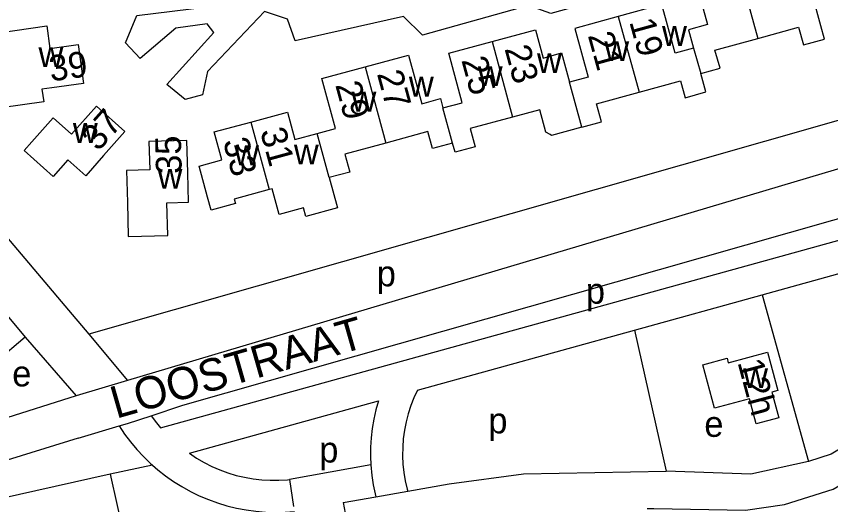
# Model space of a CAD drawing. Extents: x 162883 to 165538, y 383986 to 385172.
# Drawn here: x 164417 to 164543.6, y 384557.3 to 384633.2 of the extents above; entities that cross this region are included whole.
import ezdxf

# ---------------------------------------------------------------- set-up
doc = ezdxf.new("R2010")
doc.units = 0
for name, color, linetype in [('BLT_Basislijn', 7, 'Continuous'), ('BLT_Bebouwing', 7, 'Continuous'), ('BLT_Centroide', 7, 'Continuous'), ('BLT_Huisnummer', 7, 'Continuous'), ('BLT_Huisnummer_ tussenligend', 7, 'Continuous'), ('BLT_Onderverdeling_panden', 7, 'Continuous'), ('BLT_Straatnaam', 7, 'Continuous')]:
    doc.layers.add(name, color=color, linetype=linetype)

msp = doc.modelspace()

# ---------------------------------------------------------------- linework, layer by layer
at = {"layer": 'BLT_Basislijn'}
for p, q in [((164553.59, 384619.51), (164428.29, 384583.78)), ((164404.43, 384611.88), (164424.57, 384588.23)), ((164553.06, 384611.91), (164434.29, 384576.61)), ((164439.44, 384569.26), (164555.69, 384601.4)), ((164533, 384589.94), (164556.66, 384596.48)), ((164513.11, 384584.44), (164533, 384589.94)), ((164533, 384589.94), (164540.17, 384564.04)), ((164424.57, 384588.23), (164428.29, 384583.78)), ((164428.29, 384583.78), (164434.29, 384576.61)), ((164479.4, 384575.12), (164513.11, 384584.44)), ((164513.11, 384584.44), (164518.06, 384562.5)), ((164418.37, 384583.33), (164426.33, 384574.22)), ((164434.29, 384576.61), (164426.33, 384574.22)), ((164426.33, 384574.22), (164414.53, 384570.51)), ((164437.95, 384571.13), (164442.92, 384572.76)), ((164443.91, 384565.3), (164473.33, 384573.44)), ((164434.29, 384569.93), (164437.95, 384571.13)), ((164433, 384569.54), (164434.29, 384569.93)), ((164426.61, 384567.64), (164433, 384569.54)), ((164426.61, 384567.64), (164401.23, 384559.81)), ((164438.18, 384563.46), (164431.59, 384562.05)), ((164472.13, 384563.52), (164459.46, 384561.22)), ((164459.46, 384561.22), (164460.12, 384557.04)), ((164467.83, 384557.63), (164472.93, 384558.53)), ((164472.93, 384558.53), (164477.88, 384559.41)), ((164467.83, 384557.63), (164468.82, 384552.21))]:
    msp.add_line(p, q, dxfattribs=at)
for points in [[(164530.02, 384655.67), (164523.39, 384654.01), (164524.91, 384648.14), (164519.33, 384646.51), (164517.95, 384644.09), (164519.33, 384638.96), (164500.12, 384633.64), (164496.67, 384634.86), (164480.18, 384630.26), (164477.19, 384633.17), (164460.34, 384629.38), (164459.19, 384632.74), (164455.61, 384633.93)], [(164455.61, 384633.93), (164446.71, 384624.64), (164445.93, 384620.98), (164443.27, 384620.28), (164440.41, 384622.61), (164447.71, 384630.68), (164446.66, 384632.04), (164441.79, 384631.37), (164436.24, 384626.66), (164433.96, 384629.09), (164435.76, 384633.33), (164449.67, 384635.02), (164451.25, 384637.34)], [(164442.92, 384572.76), (164550.7, 384603.45), (164555.04, 384604.67)], [(164479.4, 384575.12), (164478.84, 384573.92), (164478.36, 384572.7), (164477.95, 384571.44), (164477.62, 384570.16), (164477.36, 384568.87), (164477.18, 384567.56), (164477.09, 384566.24), (164477.07, 384564.92), (164477.13, 384563.6), (164477.27, 384562.29), (164477.49, 384560.99), (164477.8, 384559.7), (164477.88, 384559.41)], [(164556.18, 384575.94), (164554.59, 384573.48), (164549.66, 384568.74), (164543.71, 384565.14), (164540.17, 384564.04)], [(164473.33, 384573.44), (164472.93, 384572.03), (164472.6, 384570.61), (164472.35, 384569.16), (164472.17, 384567.71), (164472.08, 384566.25), (164472.07, 384564.79), (164472.13, 384563.52)], [(164437.95, 384571.13), (164438.79, 384570.03), (164439.44, 384569.26)], [(164515.11, 384556.74), (164516.15, 384556.71), (164530.41, 384556.48), (164536.46, 384557.35), (164544, 384559.73), (164552.89, 384564.9), (164556.58, 384566.59), (164561.28, 384567.83), (164564.73, 384567.77), (164568.27, 384566.96), (164569.42, 384569.95)], [(164433, 384569.54), (164433.85, 384568.28), (164434.76, 384567.06), (164435.74, 384565.9), (164436.78, 384564.78), (164437.87, 384563.73), (164438.18, 384563.46)], [(164443.91, 384565.3), (164445.03, 384564.55), (164446.19, 384563.87), (164447.39, 384563.26), (164448.63, 384562.72), (164449.89, 384562.26), (164451.18, 384561.87), (164452.49, 384561.56), (164453.82, 384561.33), (164455.16, 384561.17), (164456.5, 384561.1), (164457.85, 384561.11), (164459.19, 384561.19), (164459.46, 384561.22)], [(164438.18, 384563.46), (164439.02, 384562.73), (164440.22, 384561.79), (164441.47, 384560.92), (164442.76, 384560.11), (164444.09, 384559.37), (164445.46, 384558.71), (164446.87, 384558.11), (164448.3, 384557.6), (164449.75, 384557.15), (164451.23, 384556.79), (164452.73, 384556.5), (164454.24, 384556.29), (164455.75, 384556.16), (164457.27, 384556.11), (164458.8, 384556.14), (164460.27, 384556.25)], [(164472.13, 384563.52), (164472.29, 384561.87), (164472.51, 384560.42), (164472.82, 384558.99), (164472.93, 384558.53)], [(164540.17, 384564.04), (164531.21, 384562.04), (164518.06, 384562.5)], [(164477.88, 384559.41), (164484.31, 384560.55), (164495.89, 384562.12), (164518.06, 384562.5)]]:
    msp.add_lwpolyline(points, dxfattribs=at)
at = {"layer": 'BLT_Bebouwing'}
msp.add_line((164431.59, 384562.05), (164414.48, 384558.22), dxfattribs=at)
for points in [[(164532.31, 384629.76), (164538.65, 384631.51), (164539.42, 384628.74), (164542.7, 384629.65), (164542.13, 384631.7), (164540.8, 384636.52), (164537.92, 384635.73), (164535.83, 384643.33), (164529.08, 384641.47)], [(164529.08, 384641.47), (164522.34, 384639.61), (164524.46, 384631.91), (164521.53, 384631.11), (164522.32, 384628.24)], [(164522.32, 384628.24), (164519.45, 384627.44), (164517.36, 384635.02), (164510.61, 384633.16)], [(164510.61, 384633.16), (164503.86, 384631.3), (164505.94, 384623.76), (164503.02, 384622.95)], [(164422.52, 384622.06), (164420.99, 384621.85), (164421.27, 384619.89), (164414.67, 384618.96), (164413.05, 384630.47), (164416.78, 384630.99), (164421.73, 384631.69), (164422.23, 384628.2), (164426.62, 384628.82), (164427.47, 384622.76), (164422.52, 384622.06)], [(164491, 384629.27), (164497.74, 384631.09), (164498.93, 384626.68), (164501.78, 384627.5), (164503.02, 384622.95)], [(164483.34, 384618.96), (164486.34, 384619.77), (164484.26, 384627.44), (164491, 384629.27)], [(164523.45, 384624.3), (164526.43, 384625.12), (164525.65, 384627.93), (164532.31, 384629.76)], [(164471.25, 384625.34), (164477.99, 384627.16), (164480.04, 384619.61), (164482.95, 384620.4), (164483.34, 384618.96)], [(164463.8, 384614.98), (164466.62, 384615.75), (164464.52, 384623.51), (164471.25, 384625.34)], [(164513.85, 384621.42), (164520.27, 384623.19), (164520.99, 384620.54), (164524.24, 384621.44), (164523.45, 384624.3)], [(164504.94, 384615.98), (164508.01, 384616.82), (164507.24, 384619.6), (164513.85, 384621.42)], [(164430.58, 384611.54), (164427.81, 384608.42), (164425.04, 384610.88), (164422.76, 384608.32), (164418.23, 384612.36), (164419.4, 384613.68), (164422.72, 384617.41), (164425.58, 384614.87), (164429.45, 384619.23), (164433.9, 384615.27), (164430.58, 384611.54)], [(164453.46, 384616.76), (164459.15, 384618.3), (164460.3, 384614.04), (164463.8, 384614.98)], [(164504.94, 384615.98), (164500.23, 384614.68), (164500, 384614.82), (164499.35, 384615.19), (164498.4, 384618.68), (164494.18, 384617.54)], [(164456.31, 384606.27), (164450.9, 384604.8), (164451.09, 384604.11), (164447.3, 384603.08), (164446.75, 384605.09), (164445.44, 384609.92), (164448.96, 384610.87), (164447.78, 384615.22), (164453.46, 384616.76)], [(164494.18, 384617.54), (164487.6, 384615.76), (164488.37, 384612.93), (164485.27, 384612.09), (164484.83, 384613.49)], [(164484.83, 384613.49), (164481.73, 384612.65), (164481.02, 384615.27), (164474.46, 384613.49)], [(164443.67, 384608.88), (164443.54, 384613.88), (164437.63, 384613.72), (164437.75, 384609.34), (164434.15, 384609.24), (164434.28, 384604.24), (164434.42, 384598.98), (164440.56, 384599.14), (164440.42, 384604.2), (164443.8, 384604.29), (164443.67, 384608.88)], [(164474.46, 384613.49), (164468.1, 384611.77), (164468.85, 384609), (164465.65, 384608.13)], [(164465.65, 384608.13), (164466.93, 384603.42), (164462.01, 384602.08), (164461.65, 384603.42), (164457.86, 384602.39), (164456.78, 384606.4), (164456.31, 384606.27)], [(164408.59, 384595.02), (164418.37, 384583.33)], [(164418.37, 384583.33), (164413.82, 384579.48), (164414.54, 384577.89), (164410.12, 384575.95)], [(164527.53, 384580.07), (164527.72, 384579.37), (164533.84, 384581), (164535.43, 384575.04), (164534.49, 384574.79), (164535.56, 384570.8), (164532.03, 384569.86), (164530.99, 384573.77), (164525.56, 384572.32), (164523.77, 384579.06), (164527.53, 384580.07)], [(164431.59, 384562.05), (164433.77, 384552.29), (164433.61, 384550.37), (164433.07, 384548.55), (164430.45, 384545.6), (164429.76, 384545.15), (164428.97, 384544.82), (164427.31, 384544.6), (164425.5, 384544.65), (164422.79, 384544.5), (164421.7, 384544.57), (164420.15, 384545.59), (164419.06, 384547.29), (164418.44, 384548.86)]]:
    msp.add_lwpolyline(points, dxfattribs=at)
at = {"layer": 'BLT_Onderverdeling_panden'}
for p, q in [((164529.08, 384641.47), (164532.31, 384629.76)), ((164510.61, 384633.16), (164513.85, 384621.42)), ((164491, 384629.27), (164494.18, 384617.54)), ((164522.32, 384628.24), (164523.45, 384624.3)), ((164471.25, 384625.34), (164474.46, 384613.49)), ((164504.94, 384615.98), (164503.02, 384622.95)), ((164484.83, 384613.49), (164483.34, 384618.96)), ((164453.46, 384616.76), (164456.31, 384606.27)), ((164465.65, 384608.13), (164463.8, 384614.98))]:
    msp.add_line(p, q, dxfattribs=at)

# ---------------------------------------------------------------- texts
at = {"layer": 'BLT_Centroide'}
for s, p in [('w', (164517.42, 384628.59)), ('w', (164508.44, 384626.25)), ('w', (164420.45, 384625.31)), ('w', (164497.97, 384624.39)), ('w', (164488.77, 384622.36)), ('w', (164478.05, 384620.72)), ('w', (164469.12, 384618.39)), ('w', (164425.8, 384613.53)), ('w', (164450.88, 384610.06)), ('w', (164460.17, 384610.19)), ('w', (164438.97, 384606.42)), ('p', (164473.05, 384591.24)), ('p', (164505.57, 384588.54)), ('e', (164416.37, 384575.69)), ('w', (164530.03, 384575.44)), ('p', (164490.4, 384568.39)), ('e', (164523.99, 384567.85)), ('p', (164464.11, 384563.86))]:
    msp.add_text(s, height=4, dxfattribs=at).set_placement(p)
at = {"layer": 'BLT_Huisnummer'}
for s, rotation, p in [('19', 285.4132, (164512.3, 384632.35)), ('23', 285.1678, (164492.9, 384628.17)), ('39', 8.0377, (164422.38, 384623.06)), ('27', 285.1632, (164473.06, 384624.28)), ('37', 48.3408, (164429.75, 384612.07)), ('35', 91.5358, (164442.74, 384608.75)), ('33', 285.1566, (164449.11, 384613.77)), ('12h', 284.915, (164529.13, 384579.44))]:
    msp.add_text(s, height=4, rotation=rotation, dxfattribs=at).set_placement(p)
at = {"layer": 'BLT_Huisnummer_ tussenligend'}
for s, rotation, p in [('21', 285.4132, (164505.85, 384630.24)), ('25', 285.1678, (164486.19, 384626.4)), ('29', 285.1632, (164466.58, 384622.55)), ('31', 285.1632, (164454.89, 384615.35))]:
    msp.add_text(s, height=4, rotation=rotation, dxfattribs=at).set_placement(p)
at = {"layer": 'BLT_Straatnaam'}
msp.add_text('LOOSTRAAT', height=5, rotation=16.0156, dxfattribs=at).set_placement((164432.52, 384570.64))

doc.saveas('drawing.dxf')
